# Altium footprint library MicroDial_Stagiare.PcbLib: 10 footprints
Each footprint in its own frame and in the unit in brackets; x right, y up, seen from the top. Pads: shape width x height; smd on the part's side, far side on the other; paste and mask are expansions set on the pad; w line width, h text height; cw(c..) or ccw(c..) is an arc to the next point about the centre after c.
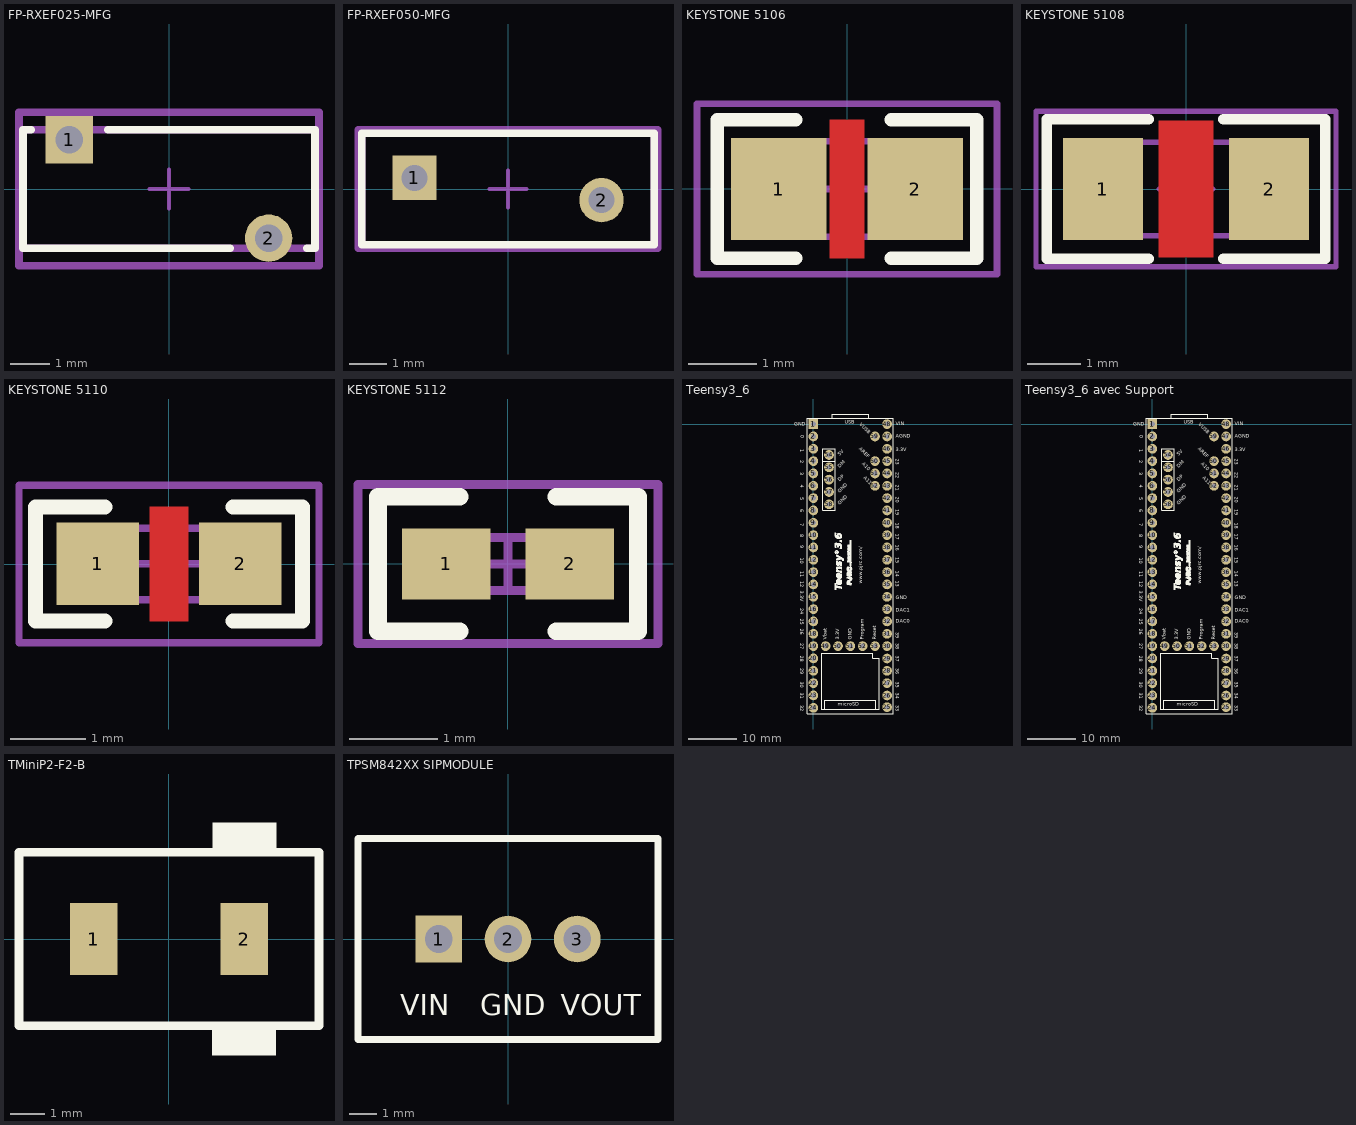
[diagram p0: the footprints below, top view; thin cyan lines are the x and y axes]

## FP-RXEF025-MFG [mm]
pads (2):
  rect 1.2x1.2 hole 0.7 paste-1000 mask+0: 1(-2.525,1.245)
  round 1.2 hole 0.7 paste-1000 mask+0: 2(2.525,-1.245)
Top Overlay:
  lines w0.2: -3.5,1.5 -3.7,1.5 -3.7,-1.5 1.55,-1.5 ; -1.55,1.5 3.7,1.5 3.7,-1.5 3.5,-1.5
Mechanical 5:
  lines w0.2: -3.8,-1.945 -3.8,1.945 3.8,1.945 3.8,-1.945 -3.8,-1.945
  text ".Designator" at 0,0.188 h1
Mechanical 13:
  lines w0.2: -3.7,-1.5 -3.7,1.5 3.7,1.5 3.7,-1.5 -3.7,-1.5
Mechanical 15:
  lines w0.2: -3.8,-1.945 -3.8,1.945 3.8,1.945 3.8,-1.945 -3.8,-1.945
Mechanical 16:
  lines w0.1: -0.5,0 0.5,0 ; 0,-0.5 0,0.5
3D body "Fuse_Littelfuse_RXEF025_eec.STEP": height 0.25, standoff 0, extent -3.8,-1.945 3.8,1.945

## FP-RXEF050-MFG [mm]
pads (2):
  rect 1.2x1.2 hole 0.7 paste-1000 mask+0: 1(-2.525,0.3)
  round 1.2 hole 0.7 paste-1000 mask+0: 2(2.525,-0.3)
Top Overlay:
  lines w0.2: -3.95,-1.5 -3.95,1.5 3.95,1.5 3.95,-1.5 -3.95,-1.5
Mechanical 5:
  lines w0.2: -4.05,-1.6 -4.05,1.6 4.05,1.6 4.05,-1.6 -4.05,-1.6
  text ".Designator" at 0,-0.001 h1
Mechanical 13:
  lines w0.2: -3.95,-1.5 -3.95,1.5 3.95,1.5 3.95,-1.5 -3.95,-1.5
Mechanical 15:
  lines w0.2: -4.05,-1.6 -4.05,1.6 4.05,1.6 4.05,-1.6 -4.05,-1.6
Mechanical 16:
  lines w0.1: -0.5,0 0.5,0 ; 0,-0.5 0,0.5
3D body "Fuse_Littelfuse_RXEF050_eec.STEP": height 0.25, standoff 0, extent -4.05,-1.6 4.05,1.6

## KEYSTONE 5106 [mm] "Replacement for 0805 zero ohm chip set"
height 0.71
pads (2):
  rect 1.4x1.5 smd: 1(-1,0) 2(1,0)
Top Layer:
  pour cut-out: -0.254,1.016 -0.254,-1.016 0.254,-1.016 0.254,1.016
Top Overlay:
  lines w0.2: -0.75,-1.016 -1.905,-1.016 -1.905,1.016 -0.75,1.016 ; 0.65,-1.016 1.905,-1.016 1.905,1.016 0.65,1.016
Mechanical 13:
  lines w0.1: -1.075,-0.7 -1.075,0.7 1.075,0.7 1.075,-0.7 -1.075,-0.7
Mechanical 15:
  lines w0.1: -0.5,0 0.5,0 ; 0,-0.5 0,0.5 ; -2.2,-1.25 -2.2,1.25 2.2,1.25 2.2,-1.25 -2.2,-1.25
3D body "keystone-PN5106.STEP": height 0.74, standoff 0.03, extent -1.003,-0.625 1.003,0.62

## KEYSTONE 5108 [mm] "Replacement for 1206 zero ohm chip set"
height 0.71
pads (2):
  rect 1.5x1.9 smd: 1(-1.55,0) 2(1.55,0)
Top Layer:
  pour cut-out: -0.508,1.27 -0.508,-1.27 0.508,-1.27 0.508,1.27
Top Overlay:
  lines w0.2: -0.7,-1.3 -2.6,-1.3 -2.6,1.3 -0.7,1.3 ; 0.7,-1.3 2.6,-1.3 2.6,1.3 0.7,1.3
Mechanical 13:
  lines w0.1: -1.675,-0.875 -1.675,0.875 1.675,0.875 1.675,-0.875 -1.675,-0.875
Mechanical 15:
  lines w0.1: -0.5,0 0.5,0 ; 0,-0.5 0,0.5 ; -2.8,-1.45 -2.8,1.45 2.8,1.45 2.8,-1.45 -2.8,-1.45
3D body "keystone-PN5108.STEP": height 0.74, standoff 0.03, extent -1.524,-0.85 1.524,0.852

## KEYSTONE 5110 [mm] "Replacement for 0603 zero ohm chip set"
height 0.7
pads (2):
  rect 1.1x1.1 smd: 1(-0.95,0) 2(0.95,0)
Top Layer:
  pour cut-out: -0.254,0.762 -0.254,-0.762 0.254,-0.762 0.254,0.762
Top Overlay:
  lines w0.2: -0.852,-0.762 -1.778,-0.762 -1.778,0.762 -0.852,0.762 ; 0.852,-0.762 1.778,-0.762 1.778,0.762 0.852,0.762
Mechanical 13:
  lines w0.1: -0.85,-0.475 0.85,-0.475 0.85,0.475 -0.85,0.475 -0.85,-0.475
Mechanical 15:
  lines w0.1: -0.475,0 0.475,0 ; 0,-0.475 0,0.475 ; -2,-1.05 2,-1.05 2,1.05 -2,1.05 -2,-1.05
3D body "keystone-PN5110.STEP": height 0.74, standoff 0.03, extent -0.775,-0.425 0.775,0.425

## KEYSTONE 5112 [mm] "Replacement for 0402 zero ohm chip set"
height 0.5
pads (2):
  rect 1x0.8 smd: 1(-0.7,0) 2(0.7,0)
Top Overlay:
  lines w0.2: -0.547,-0.762 -1.473,-0.762 -1.473,0.762 -0.547,0.762 ; 0.547,-0.762 1.473,-0.762 1.473,0.762 0.547,0.762
Mechanical 13:
  lines w0.1: -0.55,-0.3 -0.55,0.3 0.55,0.3 0.55,-0.3 -0.55,-0.3
Mechanical 15:
  lines w0.1: -0.3,0 0.3,0 ; 0,-0.3 0,0.3 ; -1.7,-0.9 -1.7,0.9 1.7,0.9 1.7,-0.9 -1.7,-0.9
3D body "keystone-PN5112.STEP": height 0.53, standoff 0.03, extent -0.5,-0.25 0.5,0.25

## Teensy3_6 [mm] "Teensy3_6 32 Bits Arduino-Compatible Microcontroleur"
pads (62):
  rect 2x2 hole 1: 1(0,0)
  round 2 hole 1: 2(0,-2.54) 3(0,-5.08) 4(0,-7.62) 5(0,-10.16) 6(0,-12.7) 7(0,-15.24) 8(0,-17.78) 9(0,-20.32) 10(0,-22.86) 11(0,-25.4) 12(0,-27.94) 13(0,-30.48) 14(0,-33.02) 15(0,-35.56) 16(0,-38.1) 17(0,-40.64) 18(0,-43.18) 19(0,-45.72) 20(0,-48.26) 21(0,-50.8) 22(0,-53.34) 23(0,-55.88) 24(0,-58.42) 25(15.208,-58.307) 26(15.208,-55.894) 27(15.208,-53.354) 28(15.208,-50.8) 29(15.208,-48.274) 30(15.208,-45.72) 31(15.208,-43.18) 32(15.208,-40.64) 33(15.208,-38.1) 34(15.208,-35.56) 35(15.208,-33.02) 36(15.208,-30.48) 37(15.208,-27.94) 38(15.208,-25.4) 39(15.208,-22.86) 40(15.208,-20.32) 41(15.208,-17.78) 42(15.208,-15.24) 43(15.208,-12.7) 44(15.208,-10.16) 45(15.208,-7.62) 46(15.208,-5.08) 47(15.208,-2.54) 48(15.208,0) 49(2.54,-45.72) 50(5.08,-45.72) 51(7.62,-45.72) 52(10.16,-45.72) 53(12.7,-45.72) 54(3.23,-6.35) 55(3.23,-8.89) 56(3.23,-11.43) 57(3.23,-13.97) 58(3.23,-16.51) 59(12.7,-2.54) 60(12.7,-7.62) 61(12.7,-10.16) 62(12.7,-12.7)
Top Overlay:
  drawing of 832 lines, arcs and shapes, not listed
  text "www.pjrc.com/" at 10.052,-32.918 h0.76
  text "GND" at 17.018,-36.068 h0.76
  text "14" at 17.018,-30.226 h0.76
  text "20" at 17.018,-14.986 h0.76
  text "16" at 17.018,-24.892 h0.76
  text "19" at 17.018,-17.526 h0.76
  text "18" at 17.018,-20.32 h0.76
  text "13" at 17.018,-32.258 h0.76
  text "15" at 17.018,-27.432 h0.76
  text "17" at 17.018,-22.606 h0.76
  text "DAC1" at 17.018,-38.624 h0.76
  text "microSD" at 5.067,-58.026 h0.76
  text "38" at 17.018,-45.166 h0.76
  text "DAC0" at 17.018,-40.91 h0.76
  text "37" at 17.018,-47.752 h0.76
  text "5V" at 5.47,-6.586 h0.76
  text "DM" at 5.47,-9.126 h0.76
  text "DP" at 5.47,-11.92 h0.76
  text "GND" at 5.47,-14.206 h0.76
  text "GND" at 5.47,-16.746 h0.76
  text "VIN" at 17.018,-0.254 h0.76
  text "AGND" at 17.018,-2.794 h0.76
  text "A11" at 10.255,-11.137 h0.76
  text "A10" at 9.954,-8.253 h0.76
  text "AREF" at 9.365,-5.166 h0.76
  text "VUSB" at 9.459,-0.139 h0.76
  text "23" at 17.018,-7.112 h0.76
  text "22" at 17.018,-9.906 h0.76
  text "21" at 17.018,-12.446 h0.76
  text "33" at 17.018,-57.912 h0.76
  text "39" at 17.018,-42.863 h0.76
  text "36" at 17.018,-50.292 h0.76
  text "35" at 17.018,-53.086 h0.76
  text "34" at 17.018,-55.372 h0.76
  text "Vbat" at 2.793,-44.45 h0.76
  text "3.3V" at 5.334,-44.45 h0.76
  text "GND" at 7.874,-44.45 h0.76
  text "Program" at 10.414,-44.45 h0.76
  text "Reset" at 12.953,-44.45 h0.76
  text "3.3V" at 17.018,-5.588 h0.76
  text "USB" at 6.441,0.089 h0.76
  text "0" at -1.881,-2.874 h0.76
  text "30" at -2.643,-53.05 h0.76
  text "27" at -2.643,-45.166 h0.76
  text "10" at -2.643,-27.512 h0.76
  text "29" at -2.643,-50.256 h0.76
  text "28" at -2.643,-47.716 h0.76
  text "31" at -2.643,-55.336 h0.76
  text "3.3V" at -2.643,-34.37 h0.76
  text "25" at -2.643,-40.132 h0.76
  text "24" at -2.643,-37.926 h0.76
  text "26" at -2.643,-42.164 h0.76
  text "12" at -2.643,-32.338 h0.76
  text "11" at -2.643,-30.306 h0.76
  text "4" at -2.643,-12.476 h0.76
  text "9" at -2.643,-24.972 h0.76
  text "8" at -2.643,-22.686 h0.76
  text "6" at -2.643,-17.556 h0.76
  text "5" at -2.643,-15.016 h0.76
  text "3" at -2.643,-9.936 h0.76
  text "2" at -2.643,-7.429 h0.76
  text "1" at -2.643,-5.132 h0.76
  text "7" at -2.643,-20.4 h0.76
  text "32" at -2.643,-57.876 h0.76
  text "GND" at -3.913,-0.39 h0.76
3D body: height 0.25, standoff 0, extent 14.345,1.51 14.345,1.51
3D body "Teensy 3.6.step": height 7.19, standoff -5.95, extent -1.27,-59.69 16.51,2.67
3D body: height 0.25, standoff 0, extent -1.627,1.51 -1.627,1.51

## Teensy3_6 avec Support [mm] "Teensy3_6 32 Bits Arduino-Compatible Microcontroleur avec support HARWIN 4 X M20-7821246 et M20-7820546"
pads (62):
  rect 2x2 hole 1: 1(0,0)
  round 2 hole 1: 2(0,-2.54) 3(0,-5.08) 4(0,-7.62) 5(0,-10.16) 6(0,-12.7) 7(0,-15.24) 8(0,-17.78) 9(0,-20.32) 10(0,-22.86) 11(0,-25.4) 12(0,-27.94) 13(0,-30.48) 14(0,-33.02) 15(0,-35.56) 16(0,-38.1) 17(0,-40.64) 18(0,-43.18) 19(0,-45.72) 20(0,-48.26) 21(0,-50.8) 22(0,-53.34) 23(0,-55.88) 24(0,-58.42) 25(15.208,-58.307) 26(15.208,-55.894) 27(15.208,-53.354) 28(15.208,-50.8) 29(15.208,-48.274) 30(15.208,-45.72) 31(15.208,-43.18) 32(15.208,-40.64) 33(15.208,-38.1) 34(15.208,-35.56) 35(15.208,-33.02) 36(15.208,-30.48) 37(15.208,-27.94) 38(15.208,-25.4) 39(15.208,-22.86) 40(15.208,-20.32) 41(15.208,-17.78) 42(15.208,-15.24) 43(15.208,-12.7) 44(15.208,-10.16) 45(15.208,-7.62) 46(15.208,-5.08) 47(15.208,-2.54) 48(15.208,0) 49(2.54,-45.72) 50(5.08,-45.72) 51(7.62,-45.72) 52(10.16,-45.72) 53(12.7,-45.72) 54(3.23,-6.35) 55(3.23,-8.89) 56(3.23,-11.43) 57(3.23,-13.97) 58(3.23,-16.51) 59(12.7,-2.54) 60(12.7,-7.62) 61(12.7,-10.16) 62(12.7,-12.7)
Top Overlay:
  drawing of 832 lines, arcs and shapes, not listed
  text "www.pjrc.com/" at 10.052,-32.918 h0.76
  text "GND" at 17.018,-36.068 h0.76
  text "14" at 17.018,-30.226 h0.76
  text "20" at 17.018,-14.986 h0.76
  text "16" at 17.018,-24.892 h0.76
  text "19" at 17.018,-17.526 h0.76
  text "18" at 17.018,-20.32 h0.76
  text "13" at 17.018,-32.258 h0.76
  text "15" at 17.018,-27.432 h0.76
  text "17" at 17.018,-22.606 h0.76
  text "DAC1" at 17.018,-38.624 h0.76
  text "microSD" at 5.067,-58.026 h0.76
  text "38" at 17.018,-45.166 h0.76
  text "DAC0" at 17.018,-40.91 h0.76
  text "37" at 17.018,-47.752 h0.76
  text "5V" at 5.47,-6.586 h0.76
  text "DM" at 5.47,-9.126 h0.76
  text "DP" at 5.47,-11.92 h0.76
  text "GND" at 5.47,-14.206 h0.76
  text "GND" at 5.47,-16.746 h0.76
  text "VIN" at 17.018,-0.254 h0.76
  text "AGND" at 17.018,-2.794 h0.76
  text "A11" at 10.255,-11.137 h0.76
  text "A10" at 9.954,-8.253 h0.76
  text "AREF" at 9.365,-5.166 h0.76
  text "VUSB" at 9.459,-0.139 h0.76
  text "23" at 17.018,-7.112 h0.76
  text "22" at 17.018,-9.906 h0.76
  text "21" at 17.018,-12.446 h0.76
  text "33" at 17.018,-57.912 h0.76
  text "39" at 17.018,-42.863 h0.76
  text "36" at 17.018,-50.292 h0.76
  text "35" at 17.018,-53.086 h0.76
  text "34" at 17.018,-55.372 h0.76
  text "Vbat" at 2.793,-44.45 h0.76
  text "3.3V" at 5.334,-44.45 h0.76
  text "GND" at 7.874,-44.45 h0.76
  text "Program" at 10.414,-44.45 h0.76
  text "Reset" at 12.953,-44.45 h0.76
  text "3.3V" at 17.018,-5.588 h0.76
  text "USB" at 6.441,0.089 h0.76
  text "0" at -1.881,-2.874 h0.76
  text "30" at -2.643,-53.05 h0.76
  text "27" at -2.643,-45.166 h0.76
  text "10" at -2.643,-27.512 h0.76
  text "29" at -2.643,-50.256 h0.76
  text "28" at -2.643,-47.716 h0.76
  text "31" at -2.643,-55.336 h0.76
  text "3.3V" at -2.643,-34.37 h0.76
  text "25" at -2.643,-40.132 h0.76
  text "24" at -2.643,-37.926 h0.76
  text "26" at -2.643,-42.164 h0.76
  text "12" at -2.643,-32.338 h0.76
  text "11" at -2.643,-30.306 h0.76
  text "4" at -2.643,-12.476 h0.76
  text "9" at -2.643,-24.972 h0.76
  text "8" at -2.643,-22.686 h0.76
  text "6" at -2.643,-17.556 h0.76
  text "5" at -2.643,-15.016 h0.76
  text "3" at -2.643,-9.936 h0.76
  text "2" at -2.643,-7.429 h0.76
  text "1" at -2.643,-5.132 h0.76
  text "7" at -2.643,-20.4 h0.76
  text "32" at -2.643,-57.876 h0.76
  text "GND" at -3.913,-0.39 h0.76
3D body "HARWIN M20-7820546.stp": height 8.6, standoff -2.9, extent 1.07,-46.97 14.17,-44.47
3D body "HARWIN M20-7821246.stp": height 8.6, standoff -2.9, extent 13.958,-29.41 16.458,1.47
3D body "HARWIN M20-7821246.stp": height 8.6, standoff -2.9, extent 13.958,-59.89 16.458,-29.01
3D body "HARWIN M20-7821246.stp": height 8.6, standoff -2.9, extent -1.25,-29.41 1.25,1.47
3D body "Teensy 3.6.step": height 15.69, standoff 2.55, extent -1.27,-59.69 16.51,2.67
3D body: height 0.25, standoff 0, extent 14.345,1.51 14.345,1.51
3D body: height 0.25, standoff 0, extent -1.627,1.51 -1.627,1.51
3D body "HARWIN M20-7821246.stp": height 8.6, standoff -2.9, extent -1.25,-59.89 1.25,-29.01

## TMiniP2-F2-B [mm] "DIODE, ZENER, 2W"
pads (2):
  rect 1.4x2.1 smd: 1(-2.2,0) 2(2.2,0)
Top Overlay:
  rectangle: 1.275,2.512 3.148,3.405
  region: 3.125,-2.512 1.252,-2.512 1.252,-3.405 3.125,-3.405
  region: -3.125,2.512
  lines w0.254: -4.39,-2.54 -4.39,0 -4.39,2.54 4.39,2.54 4.39,-2.54 -4.39,-2.54

## TPSM842XX SIPMODULE [mm] "TPSM842XX SIPMODULE (EAB0003A) TO-220 PowerModule"
height 11.1
pads (3):
  rect 1.71x1.71 hole 1.01: 1(-2.54,0)
  round 1.71 hole 1.01: 2(0,0) 3(2.54,0)
Top Overlay:
  lines w0.254: -5.5,-3.685 5.5,-3.685 5.5,3.685 -5.5,3.685 -5.5,-3.685
  text "VIN" at -3.944,-2.794 h0.76
  text "VOUT" at 1.938,-2.794 h0.76
  text "GND" at -1.016,-2.794 h0.76
3D body "TPSM84203.stp": height 12, standoff -3.1, extent -5,-3.33 5,3.855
